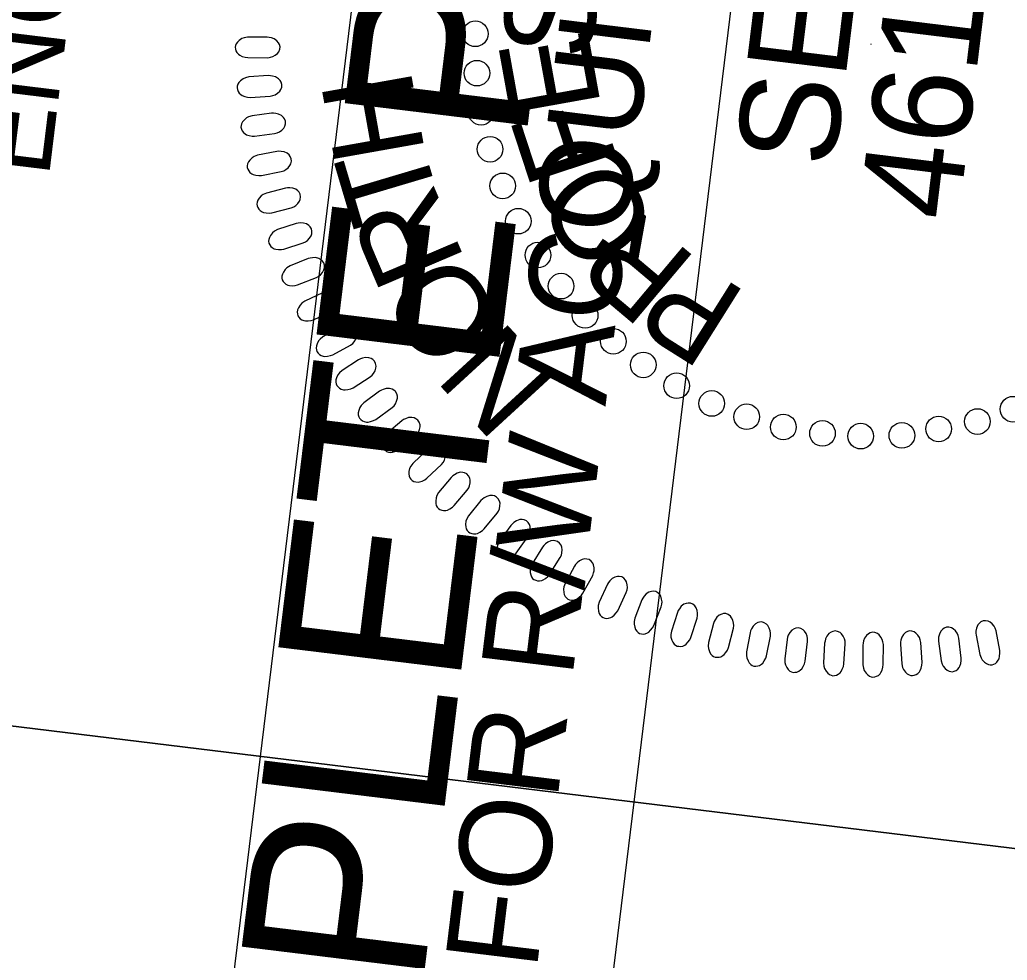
# Model space of a CAD drawing. Extents: x 480792 to 482083, y 490046 to 491850.
# Drawn here: x 481058.8 to 481120.5, y 491710 to 491768.8 of the extents above; entities that cross this region are included whole.
import ezdxf

# ---------------------------------------------------------------- set-up
doc = ezdxf.new("R2010")
doc.units = 0
for name, color, linetype in [('Sheet PE Seal Cell', 7, 'Continuous'), ('Sheet Plan CELL', 7, 'Continuous'), ('Sheet Sticker Incomplete CELL', 7, 'Continuous')]:
    doc.layers.add(name, color=color, linetype=linetype)

msp = doc.modelspace()

# ---------------------------------------------------------------- linework, layer by layer
at = {"layer": 'Sheet PE Seal Cell'}
msp.add_line((481111.972, 491767.272), (481112.018, 491767.267), dxfattribs=at)
for points in [[(481074.272, 491767.701), (481073.045, 491767.696), (481072.826, 491767.658), (481072.687, 491767.605), (481072.517, 491767.492), (481072.408, 491767.395), (481072.329, 491767.283), (481072.289, 491767.177), (481072.269, 491767.065), (481072.29, 491766.953), (481072.32, 491766.834), (481072.38, 491766.729), (481072.481, 491766.625), (481072.561, 491766.566), (481072.711, 491766.499), (481072.89, 491766.44), (481073.05, 491766.418), (481074.306, 491766.415), (481074.476, 491766.438), (481074.616, 491766.484), (481074.775, 491766.574), (481074.914, 491766.686), (481074.993, 491766.784), (481075.053, 491766.941), (481075.072, 491767.091), (481075.032, 491767.24), (481074.981, 491767.345), (481074.881, 491767.471), (481074.711, 491767.59), (481074.531, 491767.657), (481074.402, 491767.686)], [(481074.348, 491765.293), (481073.125, 491765.211), (481072.908, 491765.159), (481072.772, 491765.098), (481072.611, 491764.974), (481072.508, 491764.87), (481072.435, 491764.753), (481072.403, 491764.646), (481072.39, 491764.533), (481072.417, 491764.422), (481072.456, 491764.305), (481072.522, 491764.204), (481072.629, 491764.106), (481072.712, 491764.052), (481072.866, 491763.995), (481073.049, 491763.947), (481073.21, 491763.935), (481074.464, 491764.012), (481074.632, 491764.045), (481074.768, 491764.099), (481074.921, 491764.2), (481075.053, 491764.321), (481075.126, 491764.423), (481075.175, 491764.584), (481075.185, 491764.734), (481075.135, 491764.881), (481075.079, 491764.982), (481074.971, 491765.102), (481074.794, 491765.21), (481074.61, 491765.265), (481074.479, 491765.286)], [(481074.538, 491762.947), (481073.321, 491762.789), (481073.109, 491762.723), (481072.976, 491762.653), (481072.823, 491762.52), (481072.727, 491762.41), (481072.662, 491762.288), (481072.636, 491762.179), (481072.631, 491762.065), (481072.665, 491761.957), (481072.71, 491761.842), (481072.783, 491761.746), (481072.896, 491761.655), (481072.982, 491761.606), (481073.14, 491761.559), (481073.325, 491761.523), (481073.486, 491761.521), (481074.733, 491761.676), (481074.898, 491761.72), (481075.031, 491761.783), (481075.178, 491761.892), (481075.302, 491762.021), (481075.368, 491762.128), (481075.408, 491762.292), (481075.408, 491762.442), (481075.349, 491762.586), (481075.286, 491762.683), (481075.171, 491762.796), (481074.987, 491762.892), (481074.8, 491762.936), (481074.669, 491762.949)], [(481074.871, 491760.555), (481073.667, 491760.321), (481073.459, 491760.243), (481073.332, 491760.164), (481073.186, 491760.022), (481073.097, 491759.906), (481073.04, 491759.781), (481073.021, 491759.67), (481073.023, 491759.556), (481073.064, 491759.449), (481073.116, 491759.339), (481073.195, 491759.247), (481073.313, 491759.163), (481073.403, 491759.12), (481073.562, 491759.082), (481073.75, 491759.058), (481073.911, 491759.066), (481075.146, 491759.299), (481075.308, 491759.354), (481075.436, 491759.424), (481075.576, 491759.543), (481075.691, 491759.679), (481075.751, 491759.79), (481075.78, 491759.956), (481075.771, 491760.106), (481075.703, 491760.245), (481075.634, 491760.339), (481075.512, 491760.444), (481075.323, 491760.529), (481075.134, 491760.561), (481075.001, 491760.566)], [(481075.414, 491758.272), (481074.227, 491757.962), (481074.024, 491757.87), (481073.902, 491757.785), (481073.767, 491757.634), (481073.685, 491757.512), (481073.636, 491757.383), (481073.624, 491757.272), (481073.634, 491757.158), (481073.681, 491757.055), (481073.74, 491756.947), (481073.824, 491756.86), (481073.947, 491756.784), (481074.039, 491756.747), (481074.201, 491756.719), (481074.39, 491756.707), (481074.55, 491756.725), (481075.768, 491757.035), (481075.926, 491757.1), (481076.05, 491757.179), (481076.182, 491757.306), (481076.288, 491757.449), (481076.341, 491757.563), (481076.36, 491757.731), (481076.341, 491757.88), (481076.264, 491758.014), (481076.19, 491758.103), (481076.061, 491758.201), (481075.867, 491758.275), (481075.676, 491758.294), (481075.543, 491758.29)], [(481076.084, 491756.057), (481074.918, 491755.674), (481074.722, 491755.569), (481074.605, 491755.476), (481074.479, 491755.317), (481074.406, 491755.19), (481074.365, 491755.058), (481074.36, 491754.946), (481074.376, 491754.834), (481074.43, 491754.733), (481074.495, 491754.629), (481074.585, 491754.549), (481074.712, 491754.48), (481074.807, 491754.449), (481074.97, 491754.431), (481075.159, 491754.431), (481075.318, 491754.459), (481076.513, 491754.845), (481076.668, 491754.919), (481076.787, 491755.006), (481076.91, 491755.141), (481077.008, 491755.291), (481077.053, 491755.408), (481077.06, 491755.576), (481077.033, 491755.724), (481076.948, 491755.854), (481076.868, 491755.938), (481076.734, 491756.027), (481076.536, 491756.088), (481076.344, 491756.095), (481076.211, 491756.084)], [(481076.838, 491753.866), (481075.699, 491753.41), (481075.508, 491753.294), (481075.399, 491753.194), (481075.283, 491753.027), (481075.217, 491752.896), (481075.184, 491752.762), (481075.187, 491752.65), (481075.21, 491752.538), (481075.27, 491752.442), (481075.342, 491752.342), (481075.436, 491752.267), (481075.568, 491752.207), (481075.664, 491752.181), (481075.828, 491752.174), (481076.017, 491752.185), (481076.174, 491752.224), (481077.343, 491752.684), (481077.492, 491752.767), (481077.605, 491752.861), (481077.719, 491753.003), (481077.808, 491753.16), (481077.846, 491753.279), (481077.843, 491753.448), (481077.806, 491753.594), (481077.713, 491753.718), (481077.628, 491753.796), (481077.488, 491753.877), (481077.286, 491753.925), (481077.095, 491753.921), (481076.963, 491753.901)], [(481077.727, 491751.725), (481076.619, 491751.199), (481076.436, 491751.071), (481076.333, 491750.964), (481076.227, 491750.79), (481076.17, 491750.655), (481076.146, 491750.52), (481076.155, 491750.408), (481076.186, 491750.298), (481076.251, 491750.205), (481076.33, 491750.11), (481076.429, 491750.041), (481076.564, 491749.989), (481076.661, 491749.97), (481076.826, 491749.973), (481077.013, 491749.997), (481077.167, 491750.044), (481078.306, 491750.577), (481078.449, 491750.67), (481078.556, 491750.771), (481078.661, 491750.92), (481078.739, 491751.081), (481078.77, 491751.203), (481078.756, 491751.371), (481078.71, 491751.514), (481078.61, 491751.632), (481078.52, 491751.705), (481078.376, 491751.778), (481078.171, 491751.812), (481077.979, 491751.796), (481077.85, 491751.768)], [(481078.829, 491749.575), (481077.756, 491748.98), (481077.582, 491748.841), (481077.485, 491748.728), (481077.391, 491748.547), (481077.343, 491748.409), (481077.327, 491748.272), (481077.343, 491748.161), (481077.38, 491748.054), (481077.452, 491747.965), (481077.536, 491747.875), (481077.639, 491747.813), (481077.777, 491747.77), (481077.876, 491747.756), (481078.04, 491747.77), (481078.225, 491747.804), (481078.376, 491747.862), (481079.478, 491748.465), (481079.616, 491748.568), (481079.716, 491748.674), (481079.812, 491748.83), (481079.88, 491748.996), (481079.903, 491749.12), (481079.879, 491749.286), (481079.823, 491749.426), (481079.716, 491749.538), (481079.622, 491749.604), (481079.473, 491749.668), (481079.267, 491749.69), (481079.077, 491749.662), (481078.949, 491749.625)], [(481079.979, 491747.54), (481078.946, 491746.879), (481078.782, 491746.729), (481078.692, 491746.61), (481078.61, 491746.424), (481078.569, 491746.284), (481078.563, 491746.146), (481078.586, 491746.036), (481078.63, 491745.931), (481078.707, 491745.847), (481078.797, 491745.763), (481078.903, 491745.706), (481079.044, 491745.672), (481079.143, 491745.665), (481079.306, 491745.689), (481079.489, 491745.735), (481079.636, 491745.802), (481080.698, 491746.473), (481080.829, 491746.584), (481080.922, 491746.697), (481081.008, 491746.858), (481081.065, 491747.028), (481081.08, 491747.153), (481081.046, 491747.317), (481080.982, 491747.454), (481080.867, 491747.558), (481080.769, 491747.62), (481080.617, 491747.673), (481080.41, 491747.682), (481080.222, 491747.642), (481080.097, 491747.597)], [(481081.29, 491745.579), (481080.301, 491744.854), (481080.145, 491744.695), (481080.063, 491744.57), (481079.993, 491744.379), (481079.962, 491744.236), (481079.964, 491744.099), (481079.994, 491743.99), (481080.044, 491743.888), (481080.126, 491743.81), (481080.221, 491743.731), (481080.331, 491743.681), (481080.474, 491743.656), (481080.573, 491743.654), (481080.734, 491743.689), (481080.914, 491743.747), (481081.055, 491743.823), (481082.074, 491744.56), (481082.198, 491744.677), (481082.283, 491744.796), (481082.359, 491744.963), (481082.406, 491745.137), (481082.413, 491745.262), (481082.368, 491745.424), (481082.296, 491745.556), (481082.175, 491745.653), (481082.073, 491745.708), (481081.918, 491745.752), (481081.711, 491745.748), (481081.526, 491745.696), (481081.404, 491745.644)], [(481082.686, 491743.734), (481081.744, 491742.949), (481081.599, 491742.779), (481081.526, 491742.65), (481081.467, 491742.455), (481081.445, 491742.31), (481081.456, 491742.173), (481081.492, 491742.067), (481081.549, 491741.968), (481081.635, 491741.895), (481081.735, 491741.822), (481081.848, 491741.78), (481081.992, 491741.763), (481082.091, 491741.769), (481082.25, 491741.812), (481082.425, 491741.882), (481082.563, 491741.966), (481083.533, 491742.765), (481083.648, 491742.891), (481083.727, 491743.015), (481083.792, 491743.186), (481083.827, 491743.362), (481083.827, 491743.487), (481083.772, 491743.647), (481083.691, 491743.774), (481083.565, 491743.863), (481083.46, 491743.912), (481083.302, 491743.946), (481083.095, 491743.929), (481082.914, 491743.866), (481082.796, 491743.805)], [(481084.264, 491741.916), (481083.373, 491741.073), (481083.24, 491740.895), (481083.174, 491740.761), (481083.128, 491740.563), (481083.115, 491740.417), (481083.134, 491740.281), (481083.177, 491740.178), (481083.24, 491740.082), (481083.331, 491740.014), (481083.436, 491739.949), (481083.55, 491739.913), (481083.695, 491739.906), (481083.794, 491739.917), (481083.949, 491739.971), (481084.121, 491740.051), (481084.252, 491740.144), (481085.17, 491741.002), (481085.278, 491741.135), (481085.348, 491741.264), (481085.402, 491741.439), (481085.426, 491741.616), (481085.417, 491741.742), (481085.353, 491741.897), (481085.265, 491742.019), (481085.133, 491742.1), (481085.025, 491742.142), (481084.865, 491742.166), (481084.66, 491742.136), (481084.483, 491742.062), (481084.369, 491741.994)], [(481085.769, 491740.196), (481084.983, 491739.255), (481084.872, 491739.062), (481084.822, 491738.921), (481084.8, 491738.719), (481084.804, 491738.573), (481084.839, 491738.44), (481084.894, 491738.342), (481084.967, 491738.255), (481085.066, 491738.198), (481085.177, 491738.145), (481085.296, 491738.123), (481085.44, 491738.133), (481085.537, 491738.156), (481085.684, 491738.228), (481085.846, 491738.328), (481085.965, 491738.435), (481086.776, 491739.396), (481086.867, 491739.54), (481086.922, 491739.676), (481086.955, 491739.856), (481086.959, 491740.035), (481086.934, 491740.159), (481086.853, 491740.305), (481086.751, 491740.416), (481086.61, 491740.481), (481086.498, 491740.51), (481086.337, 491740.515), (481086.137, 491740.461), (481085.97, 491740.367), (481085.864, 491740.286)], [(481087.63, 491738.745), (481086.852, 491737.797), (481086.741, 491737.604), (481086.693, 491737.463), (481086.671, 491737.261), (481086.677, 491737.114), (481086.713, 491736.982), (481086.769, 491736.885), (481086.843, 491736.798), (481086.943, 491736.742), (481087.054, 491736.69), (481087.173, 491736.669), (481087.317, 491736.68), (481087.414, 491736.703), (481087.561, 491736.777), (481087.721, 491736.877), (481087.839, 491736.986), (481088.642, 491737.953), (481088.733, 491738.098), (481088.787, 491738.235), (481088.818, 491738.415), (481088.82, 491738.594), (481088.796, 491738.717), (481088.712, 491738.863), (481088.609, 491738.973), (481088.469, 491739.037), (481088.356, 491739.065), (481088.194, 491739.069), (481087.995, 491739.014), (481087.829, 491738.918), (481087.723, 491738.836)], [(481089.506, 491737.203), (481088.788, 491736.208), (481088.691, 491736.008), (481088.651, 491735.864), (481088.643, 491735.661), (481088.658, 491735.515), (481088.702, 491735.385), (481088.764, 491735.292), (481088.843, 491735.21), (481088.946, 491735.161), (481089.06, 491735.115), (481089.18, 491735.102), (481089.323, 491735.122), (481089.418, 491735.152), (481089.56, 491735.234), (481089.714, 491735.344), (481089.826, 491735.461), (481090.566, 491736.476), (481090.647, 491736.626), (481090.692, 491736.766), (481090.713, 491736.948), (481090.704, 491737.127), (481090.671, 491737.248), (481090.579, 491737.389), (481090.469, 491737.492), (481090.325, 491737.547), (481090.211, 491737.568), (481090.049, 491737.561), (481089.853, 491737.494), (481089.694, 491737.387), (481089.594, 491737.3)], [(481091.48, 491735.845), (481090.826, 491734.807), (481090.741, 491734.601), (481090.71, 491734.455), (481090.715, 491734.252), (481090.739, 491734.107), (481090.792, 491733.98), (481090.859, 491733.891), (481090.943, 491733.814), (481091.049, 491733.771), (481091.166, 491733.733), (481091.286, 491733.728), (481091.428, 491733.756), (481091.521, 491733.792), (481091.658, 491733.883), (481091.804, 491734.003), (481091.908, 491734.126), (481092.584, 491735.186), (481092.655, 491735.341), (481092.691, 491735.483), (481092.7, 491735.666), (481092.679, 491735.844), (481092.64, 491735.963), (481092.539, 491736.098), (481092.423, 491736.194), (481092.275, 491736.239), (481092.16, 491736.253), (481092, 491736.237), (481091.808, 491736.157), (481091.656, 491736.041), (481091.561, 491735.947)], [(481093.469, 491734.656), (481092.882, 491733.579), (481092.81, 491733.368), (481092.789, 491733.221), (481092.806, 491733.018), (481092.839, 491732.875), (481092.9, 491732.752), (481092.973, 491732.667), (481093.062, 491732.595), (481093.169, 491732.559), (481093.289, 491732.528), (481093.409, 491732.53), (481093.548, 491732.568), (481093.64, 491732.609), (481093.77, 491732.709), (481093.908, 491732.838), (481094.004, 491732.967), (481094.612, 491734.067), (481094.673, 491734.226), (481094.701, 491734.371), (481094.699, 491734.553), (481094.667, 491734.73), (481094.62, 491734.847), (481094.511, 491734.975), (481094.389, 491735.063), (481094.239, 491735.1), (481094.122, 491735.106), (481093.963, 491735.079), (481093.778, 491734.987), (481093.632, 491734.862), (481093.544, 491734.762)], [(481095.536, 491733.521), (481095.018, 491732.409), (481094.959, 491732.194), (481094.947, 491732.046), (481094.977, 491731.845), (481095.019, 491731.704), (481095.087, 491731.584), (481095.165, 491731.505), (481095.258, 491731.439), (481095.368, 491731.41), (481095.489, 491731.386), (481095.609, 491731.396), (481095.746, 491731.442), (481095.834, 491731.49), (481095.959, 491731.597), (481096.088, 491731.734), (481096.176, 491731.869), (481096.714, 491733.005), (481096.765, 491733.168), (481096.783, 491733.314), (481096.769, 491733.496), (481096.726, 491733.67), (481096.673, 491733.784), (481096.556, 491733.904), (481096.428, 491733.985), (481096.276, 491734.012), (481096.16, 491734.011), (481096.003, 491733.975), (481095.823, 491733.872), (481095.686, 491733.737), (481095.604, 491733.632)], [(481097.689, 491732.549), (481097.242, 491731.406), (481097.197, 491731.188), (481097.194, 491731.039), (481097.237, 491730.84), (481097.288, 491730.703), (481097.363, 491730.587), (481097.446, 491730.512), (481097.543, 491730.452), (481097.654, 491730.43), (481097.777, 491730.414), (481097.897, 491730.432), (481098.03, 491730.487), (481098.115, 491730.539), (481098.232, 491730.654), (481098.353, 491730.8), (481098.432, 491730.94), (481098.898, 491732.107), (481098.938, 491732.273), (481098.947, 491732.42), (481098.922, 491732.601), (481098.869, 491732.772), (481098.807, 491732.882), (481098.683, 491732.995), (481098.551, 491733.068), (481098.397, 491733.085), (481098.281, 491733.077), (481098.127, 491733.03), (481097.954, 491732.916), (481097.825, 491732.773), (481097.751, 491732.663)], [(481099.906, 491731.763), (481099.532, 491730.595), (481099.5, 491730.374), (481099.506, 491730.225), (481099.562, 491730.029), (481099.621, 491729.895), (481099.704, 491729.785), (481099.791, 491729.715), (481099.891, 491729.662), (481100.004, 491729.647), (481100.127, 491729.639), (481100.245, 491729.663), (481100.375, 491729.727), (481100.457, 491729.784), (481100.567, 491729.906), (481100.679, 491730.059), (481100.748, 491730.204), (481101.14, 491731.399), (481101.17, 491731.567), (481101.169, 491731.714), (481101.133, 491731.893), (481101.069, 491732.06), (481101.001, 491732.166), (481100.87, 491732.271), (481100.733, 491732.335), (481100.578, 491732.343), (481100.464, 491732.327), (481100.312, 491732.271), (481100.146, 491732.147), (481100.027, 491731.996), (481099.959, 491731.881)], [(481102.152, 491731.065), (481101.852, 491729.875), (481101.834, 491729.654), (481101.85, 491729.505), (481101.918, 491729.313), (481101.985, 491729.183), (481102.074, 491729.078), (481102.166, 491729.014), (481102.27, 491728.967), (481102.383, 491728.959), (481102.507, 491728.959), (481102.623, 491728.991), (481102.749, 491729.063), (481102.826, 491729.125), (481102.928, 491729.254), (481103.03, 491729.413), (481103.091, 491729.562), (481103.406, 491730.779), (481103.426, 491730.949), (481103.416, 491731.095), (481103.369, 491731.271), (481103.294, 491731.434), (481103.219, 491731.535), (481103.082, 491731.632), (481102.941, 491731.688), (481102.787, 491731.686), (481102.673, 491731.663), (481102.526, 491731.598), (481102.368, 491731.462), (481102.259, 491731.305), (481102.199, 491731.187)], [(481104.444, 491730.496), (481104.219, 491729.291), (481104.215, 491729.068), (481104.241, 491728.921), (481104.32, 491728.734), (481104.395, 491728.607), (481104.491, 491728.509), (481104.587, 491728.45), (481104.693, 491728.41), (481104.807, 491728.41), (481104.931, 491728.417), (481105.044, 491728.456), (481105.165, 491728.535), (481105.239, 491728.603), (481105.332, 491728.737), (481105.424, 491728.903), (481105.475, 491729.055), (481105.714, 491730.289), (481105.723, 491730.46), (481105.704, 491730.605), (481105.645, 491730.779), (481105.561, 491730.937), (481105.48, 491731.033), (481105.336, 491731.121), (481105.193, 491731.168), (481105.039, 491731.156), (481104.927, 491731.126), (481104.783, 491731.052), (481104.635, 491730.907), (481104.535, 491730.743), (481104.483, 491730.621)], [(481118.569, 491730.336), (481118.804, 491729.132), (481118.882, 491728.924), (481118.959, 491728.797), (481119.103, 491728.652), (481119.219, 491728.563), (481119.344, 491728.506), (481119.454, 491728.487), (481119.568, 491728.489), (481119.674, 491728.53), (481119.786, 491728.582), (481119.877, 491728.66), (481119.961, 491728.779), (481120.005, 491728.868), (481120.042, 491729.028), (481120.066, 491729.216), (481120.058, 491729.377), (481119.825, 491730.612), (481119.771, 491730.773), (481119.7, 491730.902), (481119.582, 491731.041), (481119.445, 491731.157), (481119.334, 491731.217), (481119.169, 491731.245), (481119.018, 491731.236), (481118.879, 491731.169), (481118.786, 491731.1), (481118.68, 491730.978), (481118.595, 491730.789), (481118.563, 491730.6), (481118.559, 491730.466)], [(481106.762, 491730.082), (481106.613, 491728.864), (481106.624, 491728.642), (481106.658, 491728.497), (481106.749, 491728.315), (481106.832, 491728.194), (481106.934, 491728.102), (481107.033, 491728.05), (481107.142, 491728.016), (481107.255, 491728.023), (481107.378, 491728.037), (481107.489, 491728.084), (481107.605, 491728.17), (481107.674, 491728.242), (481107.759, 491728.383), (481107.84, 491728.554), (481107.882, 491728.709), (481108.042, 491729.956), (481108.04, 491730.126), (481108.012, 491730.271), (481107.943, 491730.44), (481107.849, 491730.592), (481107.762, 491730.683), (481107.613, 491730.762), (481107.467, 491730.8), (481107.314, 491730.778), (481107.204, 491730.741), (481107.066, 491730.658), (481106.926, 491730.504), (481106.838, 491730.334), (481106.792, 491730.209)], [(481109.109, 491729.849), (481109.036, 491728.624), (481109.061, 491728.403), (481109.104, 491728.26), (481109.206, 491728.084), (481109.297, 491727.968), (481109.404, 491727.882), (481109.506, 491727.837), (481109.617, 491727.81), (481109.73, 491727.824), (481109.852, 491727.847), (481109.959, 491727.899), (481110.07, 491727.993), (481110.134, 491728.069), (481110.21, 491728.215), (481110.28, 491728.39), (481110.312, 491728.548), (481110.394, 491729.802), (481110.381, 491729.973), (481110.344, 491730.114), (481110.264, 491730.279), (481110.161, 491730.425), (481110.069, 491730.511), (481109.916, 491730.58), (481109.767, 491730.609), (481109.616, 491730.577), (481109.508, 491730.534), (481109.376, 491730.442), (481109.246, 491730.28), (481109.168, 491730.104), (481109.131, 491729.977)], [(481111.492, 491729.723), (481111.496, 491728.496), (481111.535, 491728.277), (481111.587, 491728.138), (481111.7, 491727.968), (481111.798, 491727.859), (481111.911, 491727.78), (481112.015, 491727.741), (481112.128, 491727.721), (481112.239, 491727.741), (481112.359, 491727.772), (481112.464, 491727.831), (481112.568, 491727.932), (481112.628, 491728.012), (481112.694, 491728.162), (481112.753, 491728.342), (481112.775, 491728.501), (481112.778, 491729.758), (481112.755, 491729.927), (481112.709, 491730.067), (481112.619, 491730.226), (481112.507, 491730.365), (481112.409, 491730.445), (481112.252, 491730.504), (481112.102, 491730.523), (481111.953, 491730.483), (481111.848, 491730.432), (481111.721, 491730.332), (481111.603, 491730.162), (481111.536, 491729.982), (481111.507, 491729.853)], [(481113.841, 491729.772), (481113.923, 491728.548), (481113.974, 491728.332), (481114.035, 491728.196), (481114.159, 491728.034), (481114.263, 491727.931), (481114.38, 491727.859), (481114.487, 491727.826), (481114.601, 491727.814), (481114.711, 491727.841), (481114.828, 491727.879), (481114.929, 491727.945), (481115.027, 491728.052), (481115.081, 491728.136), (481115.138, 491728.29), (481115.186, 491728.473), (481115.198, 491728.633), (481115.122, 491729.888), (481115.088, 491730.055), (481115.034, 491730.192), (481114.934, 491730.344), (481114.812, 491730.477), (481114.71, 491730.55), (481114.55, 491730.599), (481114.399, 491730.609), (481114.253, 491730.559), (481114.151, 491730.503), (481114.031, 491730.394), (481113.924, 491730.217), (481113.868, 491730.033), (481113.847, 491729.902)], [(481116.223, 491729.964), (481116.381, 491728.748), (481116.447, 491728.535), (481116.516, 491728.403), (481116.649, 491728.25), (481116.76, 491728.153), (481116.882, 491728.089), (481116.99, 491728.063), (481117.104, 491728.058), (481117.212, 491728.092), (481117.327, 491728.137), (481117.423, 491728.209), (481117.514, 491728.322), (481117.564, 491728.409), (481117.611, 491728.566), (481117.647, 491728.752), (481117.649, 491728.913), (481117.494, 491730.16), (481117.45, 491730.325), (481117.387, 491730.458), (481117.277, 491730.604), (481117.148, 491730.728), (481117.042, 491730.795), (481116.878, 491730.834), (481116.727, 491730.834), (481116.585, 491730.776), (481116.487, 491730.712), (481116.373, 491730.598), (481116.278, 491730.414), (481116.233, 491730.227), (481116.221, 491730.095)]]:
    msp.add_lwpolyline(points, close=True, dxfattribs=at)
for centre in [(481087.277, 491767.907), (481087.377, 491765.448), (481087.64, 491763.01), (481088.2, 491760.695), (481088.989, 491758.408), (481089.963, 491756.203), (481091.189, 491754.087), (481092.637, 491752.145), (481094.139, 491750.316), (481095.907, 491748.696), (481097.773, 491747.224), (481099.862, 491745.925), (481102.054, 491744.815), (481104.24, 491743.985), (481120.878, 491744.458), (481106.529, 491743.344), (481118.657, 491743.688), (481108.974, 491742.948), (481111.361, 491742.776), (481113.935, 491742.822), (481116.232, 491743.222)]:
    msp.add_circle(centre, 0.801, dxfattribs=at)
at = {"layer": 'Sheet Plan CELL'}
msp.add_line((481041.344, 491726.742), (481152.979, 491713.12), dxfattribs=at)
for points in [[(481041.344, 491726.742), (481053.454, 491825.994), (481165.138, 491812.366), (481153.027, 491713.102)], [(481029.215, 491627.43), (481041.344, 491726.742), (481153.027, 491713.102), (481140.874, 491613.805)]]:
    msp.add_lwpolyline(points, close=True, dxfattribs=at)
at = {"layer": 'Sheet Sticker Incomplete CELL'}
msp.add_lwpolyline([(481088.269, 491646.965), (481064.942, 491649.814), (481082.764, 491795.73), (481106.09, 491792.881)], close=True, dxfattribs=at)

# ---------------------------------------------------------------- texts
at = {"layer": 'Sheet PE Seal Cell'}
for s, height, rotation, p in [('SEAL', 6.2363, 83.01787, (481109.713, 491759.446)), ('46155', 6.2363, 83.01787, (481117.448, 491756.136)), ('S', 5.669, 84.32554, (481094.529, 491766.221)), ('E', 5.669, 100.20514, (481095.146, 491763.358)), ('H', 5.669, 100.09226, (481084.146, 491760.474)), ('F', 5.669, 108.14494, (481096.262, 491759.806)), ('T', 5.669, 106.58162, (481085.16, 491757.147)), ('O', 5.669, 124.02453, (481098.929, 491755.756)), ('R', 5.669, 113.07097, (481086.674, 491753.717)), ('R', 5.669, 139.90413, (481101.249, 491753.746)), ('O', 5.669, 126.04969, (481089.259, 491749.901)), ('P', 5.669, 147.84392, (481104.381, 491751.664)), ('N', 5.669, 132.53904, (481092.58, 491746.123))]:
    msp.add_text(s, height=height, rotation=rotation, dxfattribs=at).set_placement(p)
at = {"layer": 'Sheet Plan CELL'}
msp.add_text('ENGINEER', height=5.0001, rotation=83.03652, dxfattribs=at).set_placement((481060.619, 491758.868))
at = {"layer": 'Sheet Sticker Incomplete CELL'}
for s, height, p in [('INCOMPLETE PLANS', 11.52, (481077.74, 491657.268)), ('DO NOT USE FOR R/W ACQUISITION', 5.76, (481085.033, 491659.651))]:
    msp.add_text(s, height=height, rotation=83.03651, dxfattribs=at).set_placement(p)

doc.saveas('drawing.dxf')
